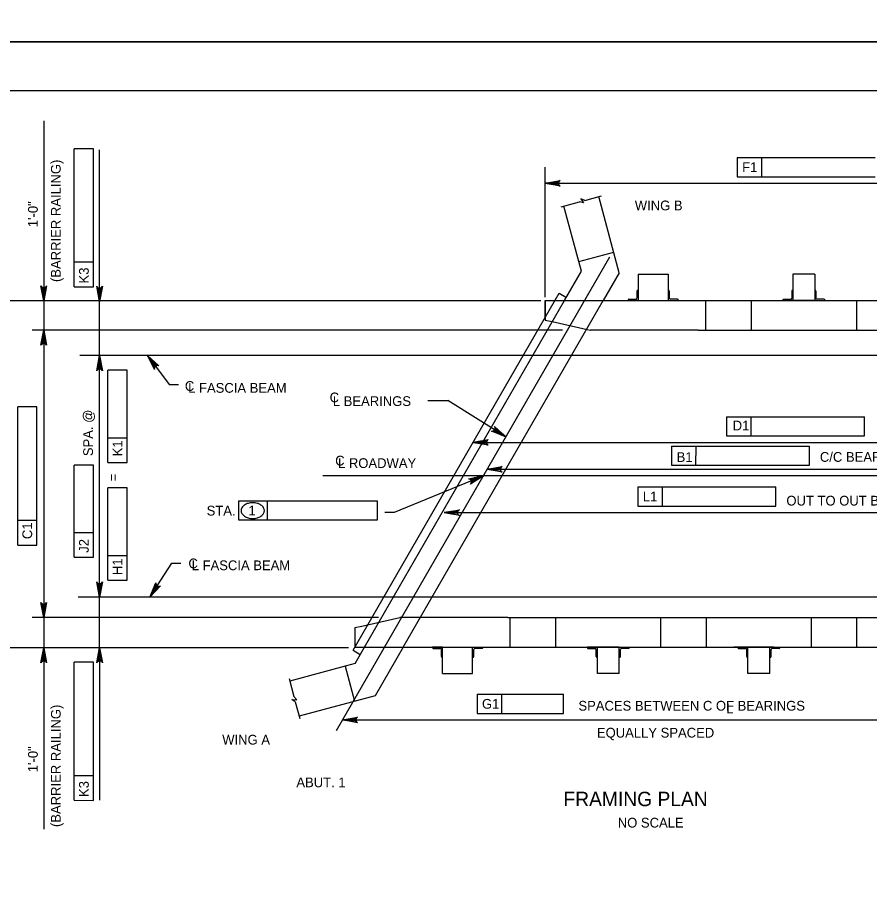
# Model space of a CAD drawing. Extents: x 638263 to 640391, y 293683 to 298655.
# Drawn here: x 638496.7 to 638759.1, y 295202.4 to 295473 of the extents above; entities that cross this region are included whole.
import ezdxf

# ---------------------------------------------------------------- set-up
doc = ezdxf.new("R2010")
doc.units = 0
for name, color, linetype in [('2', 7, 'Continuous'), ('3', 7, 'Continuous'), ('4', 7, 'Continuous'), ('PLT-BNDY', 7, 'Continuous')]:
    doc.layers.add(name, color=color, linetype=linetype)

# ---------------------------------------------------------------- blocks, each defined once
blk = doc.blocks.new('AR')
at = {"layer": '4'}
blk.add_lwpolyline([(5, 0.833375), (5, -0.833375), (0, 0)], close=True, dxfattribs=at)

msp = doc.modelspace()

# ---------------------------------------------------------------- linework, layer by layer
at = {"layer": '2'}
for p, q in [((638475.46, 295450.46), (639261.46, 295450.46)), ((638682.05, 295394.41), (638675.78, 295417.84)), ((638669.56, 295397.86), (638664.98, 295414.94)), ((638669.56, 295397.86), (638680.35, 295400.76)), ((638670.37, 295394.84), (638669.56, 295397.86)), ((638665.19, 295385.86), (638670.37, 295394.84)), ((638682.05, 295394.41), (638677.12, 295385.86)), ((638687.84, 295393.95), (638697.08, 295393.95)), ((638687.84, 295393.95), (638687.84, 295385.86)), ((638697.08, 295393.95), (638697.08, 295385.86)), ((638742.24, 295393.95), (638735.51, 295393.95)), ((638735.51, 295393.95), (638735.51, 295385.86)), ((638742.24, 295393.95), (638742.24, 295385.86)), ((638687.48, 295388.77), (638687.48, 295386.59)), ((638687.66, 295388.95), (638687.84, 295388.95)), ((638687.84, 295388.95), (638687.84, 295385.86)), ((638697.26, 295388.95), (638697.08, 295388.95)), ((638697.08, 295388.95), (638697.08, 295385.86)), ((638697.44, 295388.77), (638697.44, 295386.59)), ((638735.14, 295388.77), (638735.14, 295386.59)), ((638735.33, 295388.95), (638735.51, 295388.95)), ((638735.51, 295388.95), (638735.51, 295385.86)), ((638742.42, 295388.95), (638742.24, 295388.95)), ((638742.24, 295388.95), (638742.24, 295385.86)), ((638742.6, 295388.77), (638742.6, 295386.59)), ((638600.03, 295278.18), (638663.5, 295388.11)), ((638603.57, 295279.13), (638665.19, 295385.86)), ((638615.5, 295279.13), (638677.12, 295385.86)), ((638659.22, 295385.86), (638863.85, 295385.86)), ((638659.22, 295380.7), (638659.22, 295385.86)), ((638659.22, 295385.86), (638659.22, 295379.83)), ((638663.5, 295388.11), (638665.74, 295386.82)), ((638684.75, 295386.04), (638684.75, 295385.86)), ((638687.84, 295385.86), (638684.75, 295385.86)), ((638684.94, 295386.23), (638687.12, 295386.23)), ((638687.84, 295385.86), (638697.08, 295385.86)), ((638697.08, 295385.86), (638700.17, 295385.86)), ((638699.99, 295386.23), (638697.81, 295386.23)), ((638700.17, 295386.04), (638700.17, 295385.86)), ((638708.63, 295385.86), (638708.63, 295376.74)), ((638722.7, 295385.86), (638722.7, 295376.74)), ((638732.42, 295386.04), (638732.42, 295385.86)), ((638735.51, 295385.86), (638732.42, 295385.86)), ((638732.6, 295386.23), (638734.78, 295386.23)), ((638742.24, 295385.86), (638735.51, 295385.86)), ((638742.24, 295385.86), (638735.51, 295385.86)), ((638742.24, 295385.86), (638745.33, 295385.86)), ((638745.14, 295386.23), (638742.96, 295386.23)), ((638745.33, 295386.04), (638745.33, 295385.86)), ((638755.04, 295385.86), (638755.04, 295376.74)), ((638659.22, 295379.83), (638661.39, 295379.35)), ((638661.39, 295379.35), (638673.07, 295376.74)), ((638706.37, 295376.74), (638673.07, 295376.74)), ((638706.37, 295376.74), (638850, 295376.74)), ((638602.75, 295285.65), (638614.43, 295288.26)), ((638647.73, 295288.26), (638614.43, 295288.26)), ((638647.73, 295288.26), (638791.35, 295288.26)), ((638648.43, 295279.13), (638648.43, 295288.26)), ((638662.5, 295279.13), (638662.5, 295288.26)), ((638694.84, 295279.13), (638694.84, 295288.26)), ((638708.86, 295279.13), (638708.87, 295288.26)), ((638741.2, 295279.13), (638741.2, 295288.26)), ((638755.23, 295279.13), (638755.23, 295288.26)), ((638600.58, 295285.17), (638602.75, 295285.65)), ((638600.58, 295285.17), (638600.58, 295279.13)), ((638600.03, 295278.18), (638602.27, 295276.89)), ((638600.58, 295279.13), (638805.22, 295279.13)), ((638600.65, 295274.09), (638603.57, 295279.13)), ((638615.5, 295279.13), (638606.87, 295264.19)), ((638624.55, 295278.95), (638624.55, 295279.13)), ((638627.64, 295279.13), (638624.55, 295279.13)), ((638624.73, 295278.77), (638626.92, 295278.77)), ((638627.28, 295276.23), (638627.28, 295278.41)), ((638627.64, 295279.13), (638636.88, 295279.13)), ((638627.64, 295271.04), (638627.64, 295279.13)), ((638627.64, 295276.04), (638627.64, 295279.13)), ((638636.88, 295279.13), (638639.97, 295279.13)), ((638636.88, 295271.04), (638636.88, 295279.13)), ((638636.88, 295276.04), (638636.88, 295279.13)), ((638637.24, 295276.23), (638637.24, 295278.41)), ((638639.79, 295278.77), (638637.61, 295278.77)), ((638639.97, 295278.95), (638639.97, 295279.13)), ((638672.22, 295278.95), (638672.22, 295279.13)), ((638675.31, 295279.13), (638672.22, 295279.13)), ((638672.4, 295278.77), (638674.58, 295278.77)), ((638674.94, 295276.23), (638674.94, 295278.41)), ((638682.03, 295279.13), (638675.31, 295279.13)), ((638682.03, 295279.13), (638675.31, 295279.13)), ((638675.31, 295276.04), (638675.31, 295279.13)), ((638675.31, 295271.04), (638675.31, 295279.13)), ((638682.03, 295276.04), (638682.03, 295279.13)), ((638682.03, 295279.13), (638685.13, 295279.13)), ((638682.03, 295271.04), (638682.03, 295279.13)), ((638682.4, 295276.23), (638682.4, 295278.41)), ((638684.94, 295278.77), (638682.76, 295278.77)), ((638685.13, 295278.95), (638685.13, 295279.13)), ((638720.42, 295279.13), (638717.33, 295279.13)), ((638718.58, 295278.95), (638718.58, 295279.13)), ((638721.67, 295279.13), (638718.58, 295279.13)), ((638718.76, 295278.77), (638720.94, 295278.77)), ((638729.65, 295279.13), (638720.42, 295279.13)), ((638721.31, 295276.23), (638721.31, 295278.41)), ((638728.4, 295279.13), (638721.67, 295279.13)), ((638728.4, 295279.13), (638721.67, 295279.13)), ((638721.67, 295276.04), (638721.67, 295279.13)), ((638721.67, 295271.04), (638721.67, 295279.13)), ((638728.4, 295276.04), (638728.4, 295279.13)), ((638728.4, 295279.13), (638731.49, 295279.13)), ((638728.4, 295271.04), (638728.4, 295279.13)), ((638728.76, 295276.23), (638728.76, 295278.41)), ((638731.31, 295278.77), (638729.13, 295278.77)), ((638729.65, 295279.13), (638732.74, 295279.13)), ((638731.49, 295278.95), (638731.49, 295279.13)), ((638627.46, 295276.04), (638627.64, 295276.04)), ((638637.06, 295276.04), (638636.88, 295276.04)), ((638675.13, 295276.04), (638675.31, 295276.04)), ((638682.22, 295276.04), (638682.03, 295276.04)), ((638721.49, 295276.04), (638721.67, 295276.04)), ((638728.58, 295276.04), (638728.4, 295276.04)), ((638597.63, 295273.28), (638580.55, 295268.7)), ((638600.65, 295274.09), (638597.63, 295273.28)), ((638597.63, 295273.28), (638600.52, 295262.49)), ((638627.64, 295271.04), (638636.88, 295271.04)), ((638682.03, 295271.04), (638675.31, 295271.04)), ((638728.4, 295271.04), (638721.67, 295271.04)), ((638606.87, 295264.19), (638583.44, 295257.91))]:
    msp.add_line(p, q, dxfattribs=at)
for centre, radius, start, end in [((638687.66, 295388.77), 0.182, 90, 179.9984), ((638697.26, 295388.77), 0.182, 0.0016, 90), ((638735.33, 295388.77), 0.182, 90, 179.9984), ((638742.42, 295388.77), 0.182, 0.0016, 90), ((638684.94, 295386.04), 0.182, 90, 179.9984), ((638687.12, 295386.59), 0.364, 270, 359.9984), ((638697.81, 295386.59), 0.364, 180.0016, 270), ((638699.99, 295386.04), 0.182, 0.0016, 90), ((638732.6, 295386.04), 0.182, 90, 179.9984), ((638734.78, 295386.59), 0.364, 270, 359.9984), ((638742.96, 295386.59), 0.364, 180.0016, 270), ((638745.14, 295386.04), 0.182, 0.0016, 90), ((638624.73, 295278.95), 0.182, 180.0016, 270), ((638626.92, 295278.41), 0.364, 0.0016, 90), ((638637.61, 295278.41), 0.364, 90, 179.9984), ((638639.79, 295278.95), 0.182, 270, 359.9984), ((638672.4, 295278.95), 0.182, 180.0016, 270), ((638674.58, 295278.41), 0.364, 0.0016, 90), ((638682.76, 295278.41), 0.364, 90, 179.9984), ((638684.94, 295278.95), 0.182, 270, 359.9984), ((638718.76, 295278.95), 0.182, 180.0016, 270), ((638720.94, 295278.41), 0.364, 0.0016, 90), ((638729.13, 295278.41), 0.364, 90, 179.9984), ((638731.31, 295278.95), 0.182, 270, 359.9984), ((638627.46, 295276.23), 0.182, 180.0016, 270), ((638637.06, 295276.23), 0.182, 270, 359.9984), ((638675.13, 295276.23), 0.182, 180.0016, 270), ((638682.22, 295276.23), 0.182, 270, 359.9984), ((638721.49, 295276.23), 0.182, 180.0016, 270), ((638728.58, 295276.23), 0.182, 270, 359.9984)]:
    msp.add_arc(centre, radius, start, end, dxfattribs=at)
at = {"layer": '3'}
for p, q in [((638664.15, 295414.72), (638669.75, 295416.22)), ((638671.03, 295415.94), (638669.75, 295416.22)), ((638671.41, 295416.67), (638670.21, 295417.18)), ((638670.21, 295417.18), (638671.03, 295415.94)), ((638671.41, 295416.67), (638676.54, 295418.04)), ((638580.33, 295269.54), (638581.83, 295263.94)), ((638582.72, 295262.97), (638581.83, 295263.94)), ((638581.22, 295263.06), (638582.72, 295262.97)), ((638582.27, 295262.27), (638581.22, 295263.06)), ((638582.27, 295262.27), (638583.65, 295257.15))]:
    msp.add_line(p, q, dxfattribs=at)
at = {"layer": '4'}
for p, q in [((638504.79, 295441.18), (638504.79, 295223.12)), ((638520.1, 295432.6), (638514.2, 295432.6)), ((638514.2, 295397.64), (638514.2, 295432.6)), ((638520.1, 295390.07), (638520.1, 295432.6)), ((638521.99, 295360.32), (638521.99, 295432.24)), ((638718.36, 295429.86), (638718.35, 295423.95)), ((638718.36, 295429.86), (638725.92, 295429.86)), ((638725.91, 295423.95), (638725.92, 295429.86)), ((638725.92, 295429.86), (638760.88, 295429.86)), ((638659.22, 295386.93), (638659.22, 295426.92)), ((638718.35, 295423.95), (638760.87, 295423.95)), ((638659.22, 295421.94), (638863.85, 295421.94)), ((638679.06, 295399.25), (638633.07, 295319.6)), ((638514.2, 295390.08), (638514.2, 295397.64)), ((638520.1, 295397.64), (638514.2, 295397.64)), ((638521.99, 295388.41), (638521.99, 295391.24)), ((638514.2, 295390.08), (638520.1, 295390.07)), ((638657.9, 295385.71), (638485.21, 295385.71)), ((638664.5, 295376.74), (638501.27, 295376.74)), ((638863.96, 295368.91), (638515.91, 295368.91)), ((638536.76, 295368.91), (638543.44, 295359.98)), ((638530.46, 295364.37), (638524.55, 295364.38)), ((638524.55, 295343.53), (638524.55, 295364.38)), ((638530.46, 295335.97), (638530.46, 295364.37)), ((638521.99, 295278.98), (638521.99, 295360.32)), ((638543.44, 295359.98), (638546.27, 295359.98)), ((638623.07, 295355.07), (638629.19, 295355.07)), ((638647.11, 295343.91), (638629.19, 295355.07)), ((638502.68, 295353.08), (638496.77, 295353.09)), ((638496.77, 295318.13), (638496.77, 295353.09)), ((638502.68, 295310.56), (638502.68, 295353.08)), ((638715.06, 295350.1), (638715.05, 295344.19)), ((638715.06, 295350.1), (638722.62, 295350.1)), ((638722.61, 295344.19), (638722.62, 295350.1)), ((638722.62, 295350.1), (638757.58, 295350.1)), ((638757.57, 295344.19), (638757.58, 295350.1)), ((638524.55, 295335.97), (638524.55, 295343.53)), ((638530.46, 295343.53), (638524.55, 295343.53)), ((638715.05, 295344.19), (638757.57, 295344.19)), ((638637.01, 295342.18), (638838.3, 295342.18)), ((638698.11, 295341.07), (638698.1, 295335.16)), ((638698.11, 295341.07), (638705.67, 295341.07)), ((638705.66, 295335.16), (638705.67, 295341.07)), ((638705.67, 295341.07), (638740.63, 295341.07)), ((638740.62, 295335.16), (638740.63, 295341.07)), ((638520.1, 295335.2), (638514.2, 295335.21)), ((638514.2, 295314.36), (638514.2, 295335.21)), ((638520.1, 295306.8), (638520.1, 295335.2)), ((638524.55, 295335.97), (638530.46, 295335.97)), ((638698.1, 295335.16), (638740.62, 295335.16)), ((638883.03, 295331.93), (638590.74, 295331.93)), ((638640.19, 295331.93), (638612.72, 295320.61)), ((638641.33, 295333.9), (638825.08, 295333.9)), ((638530.46, 295328.15), (638524.55, 295328.15)), ((638524.55, 295307.31), (638524.55, 295328.15)), ((638530.46, 295299.74), (638530.46, 295328.15)), ((638687.75, 295328.47), (638687.74, 295322.57)), ((638687.75, 295328.47), (638695.31, 295328.47)), ((638695.3, 295322.57), (638695.31, 295328.47)), ((638695.31, 295328.47), (638730.27, 295328.47)), ((638730.26, 295322.57), (638730.27, 295328.47)), ((638564.92, 295324.15), (638573.66, 295324.15)), ((638564.92, 295318.24), (638564.92, 295324.15)), ((638573.66, 295318.24), (638573.66, 295324.15)), ((638573.66, 295324.15), (638607.44, 295324.15)), ((638607.44, 295324.15), (638607.44, 295318.24)), ((638687.74, 295322.57), (638730.26, 295322.57)), ((638496.77, 295310.57), (638496.77, 295318.13)), ((638502.68, 295318.12), (638496.77, 295318.13)), ((638607.44, 295318.24), (638564.92, 295318.24)), ((638633.07, 295319.6), (638594.84, 295253.38)), ((638612.72, 295320.61), (638609.88, 295320.61)), ((638628.12, 295320.55), (638823.17, 295320.55)), ((638514.2, 295306.8), (638514.2, 295314.36)), ((638520.1, 295314.36), (638514.2, 295314.36)), ((638496.77, 295310.57), (638502.68, 295310.56)), ((638524.55, 295299.75), (638524.55, 295307.31)), ((638530.46, 295307.3), (638524.55, 295307.31)), ((638514.2, 295306.8), (638520.1, 295306.8)), ((638537.51, 295294.55), (638544.21, 295304.99)), ((638544.21, 295304.99), (638547.04, 295304.99)), ((638524.55, 295299.75), (638530.46, 295299.74)), ((638825.21, 295294.55), (638515.44, 295294.55)), ((638607.93, 295288.26), (638501.27, 295288.26)), ((638598.67, 295278.98), (638485.21, 295278.98)), ((638521.99, 295276.27), (638521.99, 295273.43)), ((638520.1, 295274.51), (638514.2, 295274.51)), ((638514.2, 295239.56), (638514.2, 295274.51)), ((638520.1, 295231.99), (638520.1, 295274.51)), ((638521.99, 295273.43), (638521.99, 295232.05)), ((638638.3, 295264.65), (638645.86, 295264.65)), ((638638.3, 295264.65), (638638.3, 295258.75)), ((638645.86, 295258.75), (638645.86, 295264.65)), ((638645.86, 295264.65), (638664.81, 295264.65)), ((638664.81, 295258.75), (638664.81, 295264.65)), ((638638.3, 295258.75), (638664.81, 295258.75)), ((638596.78, 295256.73), (638780.53, 295256.73)), ((638514.2, 295232), (638514.2, 295239.56)), ((638520.1, 295239.55), (638514.2, 295239.56)), ((638514.2, 295232), (638520.1, 295231.99))]:
    msp.add_line(p, q, dxfattribs=at)
for points in [[(638659.22, 295421.94), (638663.88, 295422.81), (638663.52, 295422.56), (638663.34, 295422.25), (638663.28, 295421.94), (638663.34, 295421.62), (638663.52, 295421.31), (638663.88, 295421.06), (638659.22, 295421.94), (638663.52, 295421.31), (638663.34, 295421.62), (638659.22, 295421.94), (638663.28, 295421.94), (638663.34, 295422.25), (638659.22, 295421.94), (638663.52, 295422.56)], [(638504.79, 295385.71), (638503.91, 295390.37), (638504.16, 295390.01), (638504.47, 295389.83), (638504.79, 295389.77), (638505.1, 295389.83), (638505.41, 295390.01), (638505.66, 295390.37), (638504.79, 295385.71), (638505.41, 295390.01), (638505.1, 295389.83), (638504.79, 295385.71), (638504.79, 295389.77), (638504.47, 295389.83), (638504.79, 295385.71), (638504.16, 295390.01)], [(638521.99, 295385.57), (638521.11, 295390.23), (638521.36, 295389.87), (638521.67, 295389.69), (638521.99, 295389.64), (638522.3, 295389.69), (638522.61, 295389.87), (638522.86, 295390.23), (638521.99, 295385.57), (638522.61, 295389.87), (638522.3, 295389.69), (638521.99, 295385.57), (638521.99, 295389.64), (638521.67, 295389.69), (638521.99, 295385.57), (638521.36, 295389.87)], [(638504.79, 295376.74), (638505.66, 295372.08), (638505.41, 295372.44), (638505.1, 295372.62), (638504.79, 295372.68), (638504.47, 295372.62), (638504.16, 295372.44), (638503.91, 295372.08), (638504.79, 295376.74), (638504.16, 295372.44), (638504.47, 295372.62), (638504.79, 295376.74), (638504.79, 295372.68), (638505.1, 295372.62), (638504.79, 295376.74), (638505.41, 295372.44)], [(638521.99, 295368.91), (638522.86, 295364.25), (638522.61, 295364.61), (638522.3, 295364.79), (638521.99, 295364.85), (638521.67, 295364.79), (638521.36, 295364.61), (638521.11, 295364.25), (638521.99, 295368.91), (638521.36, 295364.61), (638521.67, 295364.79), (638521.99, 295368.91), (638521.99, 295364.85), (638522.3, 295364.79), (638521.99, 295368.91), (638522.61, 295364.61)], [(638536.76, 295368.91), (638540.25, 295365.7), (638539.84, 295365.84), (638539.48, 295365.8), (638539.2, 295365.65), (638538.98, 295365.42), (638538.84, 295365.09), (638538.85, 295364.65), (638536.76, 295368.91), (638538.84, 295365.09), (638538.98, 295365.42), (638536.76, 295368.91), (638539.2, 295365.65), (638539.48, 295365.8), (638536.76, 295368.91), (638539.84, 295365.84)], [(638647.11, 295343.91), (638642.69, 295345.63), (638643.13, 295345.65), (638643.45, 295345.82), (638643.66, 295346.06), (638643.78, 295346.35), (638643.79, 295346.71), (638643.61, 295347.12), (638647.11, 295343.91), (638643.79, 295346.71), (638643.78, 295346.35), (638647.11, 295343.91), (638643.66, 295346.06), (638643.45, 295345.82), (638647.11, 295343.91), (638643.13, 295345.65)], [(638637.01, 295342.18), (638641.67, 295343.05), (638641.31, 295342.8), (638641.13, 295342.49), (638641.08, 295342.18), (638641.13, 295341.86), (638641.31, 295341.55), (638641.67, 295341.3), (638637.01, 295342.18), (638641.31, 295341.55), (638641.13, 295341.86), (638637.01, 295342.18), (638641.08, 295342.18), (638641.13, 295342.49), (638637.01, 295342.18), (638641.31, 295342.8)], [(638641.33, 295333.9), (638645.99, 295334.77), (638645.63, 295334.52), (638645.44, 295334.21), (638645.39, 295333.9), (638645.44, 295333.58), (638645.63, 295333.27), (638645.99, 295333.02), (638641.33, 295333.9), (638645.63, 295333.27), (638645.44, 295333.58), (638641.33, 295333.9), (638645.39, 295333.9), (638645.44, 295334.21), (638641.33, 295333.9), (638645.63, 295334.52)], [(638640.19, 295331.93), (638636.21, 295329.35), (638636.45, 295329.72), (638636.5, 295330.08), (638636.44, 295330.38), (638636.27, 295330.65), (638635.98, 295330.87), (638635.55, 295330.97), (638640.19, 295331.93), (638635.98, 295330.87), (638636.27, 295330.65), (638640.19, 295331.93), (638636.44, 295330.38), (638636.5, 295330.08), (638640.19, 295331.93), (638636.45, 295329.72)], [(638628.12, 295320.55), (638632.78, 295321.42), (638632.42, 295321.18), (638632.23, 295320.86), (638632.18, 295320.55), (638632.23, 295320.24), (638632.42, 295319.93), (638632.78, 295319.68), (638628.12, 295320.55), (638632.42, 295319.93), (638632.23, 295320.24), (638628.12, 295320.55), (638632.18, 295320.55), (638632.23, 295320.86), (638628.12, 295320.55), (638632.42, 295321.18)], [(638521.99, 295294.55), (638521.11, 295299.21), (638521.36, 295298.86), (638521.67, 295298.67), (638521.99, 295298.62), (638522.3, 295298.67), (638522.61, 295298.86), (638522.86, 295299.21), (638521.99, 295294.55), (638522.61, 295298.86), (638522.3, 295298.67), (638521.99, 295294.55), (638521.99, 295298.62), (638521.67, 295298.67), (638521.99, 295294.55), (638521.36, 295298.86)], [(638537.51, 295294.55), (638539.29, 295298.95), (638539.3, 295298.51), (638539.47, 295298.19), (638539.7, 295297.97), (638539.99, 295297.85), (638540.36, 295297.83), (638540.76, 295298), (638537.51, 295294.55), (638540.36, 295297.83), (638539.99, 295297.85), (638537.51, 295294.55), (638539.7, 295297.97), (638539.47, 295298.19), (638537.51, 295294.55), (638539.3, 295298.51)], [(638504.79, 295288.26), (638503.91, 295292.92), (638504.16, 295292.56), (638504.47, 295292.37), (638504.79, 295292.32), (638505.1, 295292.37), (638505.41, 295292.56), (638505.66, 295292.92), (638504.79, 295288.26), (638505.41, 295292.56), (638505.1, 295292.37), (638504.79, 295288.26), (638504.79, 295292.32), (638504.47, 295292.37), (638504.79, 295288.26), (638504.16, 295292.56)], [(638504.79, 295278.98), (638505.66, 295274.32), (638505.41, 295274.68), (638505.1, 295274.87), (638504.79, 295274.92), (638504.47, 295274.87), (638504.16, 295274.68), (638503.91, 295274.32), (638504.79, 295278.98), (638504.16, 295274.68), (638504.47, 295274.87), (638504.79, 295278.98), (638504.79, 295274.92), (638505.1, 295274.87), (638504.79, 295278.98), (638505.41, 295274.68)], [(638522.01, 295278.98), (638522.88, 295274.32), (638522.63, 295274.68), (638522.32, 295274.87), (638522.01, 295274.92), (638521.7, 295274.87), (638521.38, 295274.68), (638521.13, 295274.32), (638522.01, 295278.98), (638521.38, 295274.68), (638521.7, 295274.87), (638522.01, 295278.98), (638522.01, 295274.92), (638522.32, 295274.87), (638522.01, 295278.98), (638522.63, 295274.68)], [(638596.78, 295256.73), (638601.44, 295257.6), (638601.08, 295257.36), (638600.89, 295257.04), (638600.84, 295256.73), (638600.89, 295256.42), (638601.08, 295256.11), (638601.44, 295255.86), (638596.78, 295256.73), (638601.08, 295256.11), (638600.89, 295256.42), (638596.78, 295256.73), (638600.84, 295256.73), (638600.89, 295257.04), (638596.78, 295256.73), (638601.08, 295257.36)]]:
    msp.add_lwpolyline(points, dxfattribs=at)
for points in [[(638521.51, 295388.41), (638522.46, 295388.41), (638521.99, 295385.57)], [(638521.51, 295366.07), (638522.46, 295366.07), (638521.99, 295368.91)], [(638538.08, 295366.36), (638538.84, 295366.92), (638536.76, 295368.91)], [(638644.95, 295345.81), (638644.45, 295345.01), (638647.11, 295343.91)], [(638639.85, 295341.7), (638639.85, 295342.65), (638637.01, 295342.18)], [(638637.39, 295331.29), (638637.75, 295330.42), (638640.19, 295331.93)], [(638630.95, 295320.08), (638630.95, 295321.02), (638628.12, 295320.55)], [(638521.51, 295297.39), (638522.46, 295297.39), (638521.99, 295294.55)], [(638521.51, 295276.27), (638522.46, 295276.27), (638521.99, 295279.1)]]:
    msp.add_lwpolyline(points, close=True, dxfattribs=at)
for centre, radius, start, end in [((638568.76, 295319.74), 3.82, 105.6708, 124.109), ((638569.15, 295318.34), 5.27, 90, 105.6708), ((638569.15, 295318.34), 5.27, 74.3292, 90), ((638569.55, 295319.74), 3.82, 55.891, 74.3292), ((638567.25, 295321.18), 1.68, 148.5507, 180), ((638567.25, 295321.18), 1.68, 180, 211.4493), ((638568.16, 295320.62), 2.75, 124.109, 148.5507), ((638570.14, 295320.62), 2.75, 31.4493, 55.891), ((638571.06, 295321.18), 1.68, 0, 31.4493), ((638571.06, 295321.18), 1.68, 328.5507, 0), ((638568.16, 295321.74), 2.75, 211.4493, 235.891), ((638568.76, 295322.62), 3.82, 235.891, 254.3292), ((638569.15, 295324.02), 5.27, 254.3292, 270), ((638569.15, 295324.02), 5.27, 270, 285.6708), ((638569.55, 295322.62), 3.82, 285.6708, 304.109), ((638570.14, 295321.74), 2.75, 304.109, 328.5507)]:
    msp.add_arc(centre, radius, start, end, dxfattribs=at)
at = {"layer": 'PLT-BNDY'}
for points in [[(638435.46, 296059.46), (639276.46, 296059.46), (639276.46, 295465.46), (638435.46, 295465.46)], [(638435.46, 295465.46), (639276.46, 295465.46), (639276.46, 294871.46), (638435.46, 294871.46)]]:
    msp.add_lwpolyline(points, close=True, dxfattribs=at)

# ---------------------------------------------------------------- block references
at = {"layer": '4', "xscale": 0.5905511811, "yscale": 0.5905511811}
for p, rotation in [((638504.79, 295385.71), 90), ((638504.79, 295376.74), -90.00000000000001), ((638504.79, 295288.26), 90), ((638504.79, 295278.98), -90.00000000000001)]:
    msp.add_blockref('AR', p, dxfattribs=dict(at, rotation=rotation))
for p in [(638641.33, 295333.9), (638596.78, 295256.73)]:
    msp.add_blockref('AR', p, dxfattribs=at)

# ---------------------------------------------------------------- texts
at = {"layer": '4'}
for s, rotation, p in [('(BARRIER RAILING)', 90, (638510.02, 295391.55)), ('F1', 359.9382, (638719.87, 295425.41)), ('1\'-0"', 90, (638502.96, 295408.43)), ('K3', 89.9382, (638518.65, 295391.1)), ('SPA. @', 90, (638519.95, 295337.94)), ('D1', 359.9382, (638716.97, 295345.87)), ('K1', 89.9382, (638529.01, 295337.9)), ('B1', 359.9382, (638699.7, 295336.17)), ('=', 90, (638527.68, 295330.18)), ('L1', 359.9382, (638689.29, 295324.02)), ('C1', 89.9382, (638501.22, 295312.4)), ('J2', 89.9382, (638518.65, 295308.2)), ('H1', 89.9382, (638529.01, 295301.31)), ('(BARRIER RAILING)', 90, (638510.02, 295223.77)), ('G1', 359.9382, (638639.75, 295260.2)), ('1\'-0"', 90, (638502.96, 295240.65)), ('K3', 89.9382, (638518.65, 295233.01))]:
    msp.add_text(s, height=3, rotation=rotation, dxfattribs=at).set_placement(p)
for s, height, p in [('WING B', 3, (638686.82, 295413.62)), ('C', 3, (638548.25, 295358.04)), ('L FASCIA BEAM', 3, (638549.27, 295357.46)), ('C', 3, (638592.83, 295354.52)), ('L BEARINGS', 3, (638593.82, 295353.39)), ('C', 3, (638594.54, 295335.06)), ('L ROADWAY', 3, (638595.42, 295334.3)), ('C/C BEARINGS', 3, (638743.82, 295336.2)), ('OUT TO OUT BEAM', 3, (638733.5, 295322.74)), ('STA.', 3, (638554.96, 295319.67)), ('1', 3, (638567.85, 295319.72)), ('C', 3, (638549.35, 295303.42)), ('L FASCIA BEAM', 3, (638550.37, 295302.84)), ('SPACES BETWEEN C OF BEARINGS', 3, (638669.45, 295259.61)), ('L', 3, (638715, 295258.78)), ('EQUALLY SPACED', 3, (638675.15, 295251.31)), ('WING A', 3, (638559.76, 295249.16)), ('ABUT. 1', 3, (638582.59, 295236.02)), ('FRAMING PLAN', 4.4292, (638664.84, 295230.2)), ('NO SCALE', 3, (638681.57, 295223.61))]:
    msp.add_text(s, height=height, dxfattribs=at).set_placement(p)

doc.saveas('drawing.dxf')
